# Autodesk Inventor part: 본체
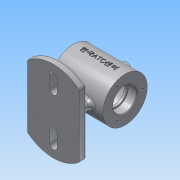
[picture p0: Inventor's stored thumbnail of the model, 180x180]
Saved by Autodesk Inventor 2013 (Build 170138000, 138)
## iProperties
Created: 2017-12
Part Number: 본체
Material: 알루미늄 6061
Document SubType Name: Modeling
Designer: Administrator
Density: 2.71 g/cm^3
Mass: 467.691 g
Surface Area: 486.474 cm^2
Volume: 172.58 cm^3
Author: Administrator
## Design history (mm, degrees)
sketch "스케치1"
  geometry: L1 (0, 30)-(0, 25); L2 (0, 25)-(-17, 25); L3 (-20, 22)-(-20, 14); L4 (-20, 14)-(-23, 14); L5 (-23, 14)-(-23, 15.7); L6 (-23.3, 16)-(-34, 16); L7 (-35, 17)-(-35, 30); L8 (-35, 30)-(0, 30); L9 (-35, 0)-(0, 0); L10 (-34, 16)-(-35, 17); A1 r 3 centre (-17, 22) between (-17, 25) and (-20, 22); A2 r 0.3 centre (-23.3, 15.7) between (-23, 15.7) and (-23.3, 16); 4 further points
  constraints: 20 end point, 6 parallel, 4 point on circle, 4 point on line, 4 tangent, 2 centre point, 2 midpoint, 2 perpendicular, 2 vertical alignment, 1 vertical
  dimensions: "d0" = 35 distance of L9.start L9.end; "d1" = 60 diameter of L8 L9; "d2" = 50 diameter of L2 L9; "d3" = 32 diameter of L6 L9; "d4" = 12 distance of point (-23, 16) point (-35, 16); "d5" = 28 diameter of L4 L9; "d6" = 3 distance of L3.end L4.end; "d7" = 3 radius of A1; "d8" = 0.3 radius of A2; "d9" = 1 distance of L6.end point (-35, 16); "d10" = 1 distance of L7.start point (-35, 16) (= d9)
revolve "회전1" sketch "스케치1" stored, may be unused: angle "d11" = 90 deg
node "작업 평면1"
sketch "스케치2"
  geometry: L1 (35, -42.426)-(35, 42.426); L2 (-35, -42.426)-(-35, 42.426); L3 (0, -55)-(0, 55); L4 (35, 0)-(-35, 0); A1 r 55 centre (0, 0) between (35, 42.426) and (-35, 42.426); A2 r 55 centre (0, 0) between (-35, -42.426) and (35, -42.426); 2 further points
  constraints: 8 end point, 6 point on circle, 3 midpoint, 2 centre point, 2 coincident, 2 parallel, 1 vertical, 1 vertical alignment, 1 other
  dimensions: "d14" = 70 distance between parallel lines of L2 L1; "d15" = 55 radius of A2
extrude "돌출1" join sketch "스케치2" distance "d16" = 10; taper "d17" = 0 deg
sketch "스케치3"
  geometry: L1 (35, -42.426)-(35, 42.426) reference; L2 (-5, 40)-(-5, 24); L3 (5, 24)-(5, 40); L4 (-5, -24)-(-5, -40); L5 (5, -40)-(5, -24); L6 (-15, 5)-(15, 5); L7 (15, -5)-(-15, -5); L8 (0, 55)-(0, -55); A1 r 55 centre (0, 0) between (-35, -42.426) and (35, -42.426) reference; A2 r 55 centre (0, 0) between (35, 42.426) and (-35, 42.426) reference; A3 r 5 centre (0, 24) between (-5, 24) and (5, 24); A4 r 5 centre (0, 40) between (5, 40) and (-5, 40); A5 r 5 centre (0, -40) between (-5, -40) and (5, -40); A6 r 5 centre (0, -24) between (5, -24) and (-5, -24); A7 r 5 centre (15, 0) between (15, -5) and (15, 5); A8 r 5 centre (-15, 0) between (-15, 5) and (-15, -5)
  constraints: 14 end point, 14 point on circle, 12 tangent, 6 centre point, 5 parallel, 2 perpendicular, 2 vertical alignment, 1 equal radius, 1 horizontal alignment, 1 other
  dimensions: "d18" = 5 radius of A4; "d20" = 16 distance of A4.centre A3.centre; "d21" = 16 distance of A5.centre A6.centre; "d22" = 24 distance of A3.centre A1.centre; "d23" = 24 distance of A6.centre A1.centre; "d24" = 5 radius of A8; "d25" = 30 distance of A7.centre A8.centre
extrude "돌출2" cut sketch "스케치3" stored distance "d26" = 10; taper "d27" = 0 deg
extrude "돌출3" join sketch "스케치3" stored distance "d28" = 10; taper "d29" = 0 deg
fillet "모깎기1" dims "d30" = 5
node "작업 평면2"
sketch "스케치4"
  geometry: C1 r 8 at (0, 0); 1 further point
  constraints: 1 centre point, 1 coincident
  dimensions: "d32" = 16 diameter of C1
extrude "돌출4" join sketch "스케치4" stored distance "d34" = 10; taper "d35" = 0 deg
hole "구멍1" diameter "d38" = 8; stored, may be unused: countersink angle "d42" = 90 deg, drill point angle "d44" = 0 deg; dims "d36" = 10, "d37" = 10, "d39" = 6, "d40" = 4, "d41" = 2, "d43" = 8
chamfer "모따기1" distance "d45" = 1; stored, may be unused: second distance "d46" = 2, angle "d47" = 45 deg
sketch "스케치5" dims "d48" = 46
  geometry: C1 r 30 at (0, 0) reference; C2 r 17 at (0, 0) reference; 2 further points
  constraints: 2 vertical alignment, 1 coincident, 2 other
hole "구멍2" sketch "스케치5" at (0, 23) diameter "d49" = 3.242; stored, may be unused: countersink angle "d53" = 90 deg, drill point angle "d55" = 118 deg; dims "d50" = 8, "d51" = 4, "d52" = 2, "d54" = 10
node "작업 평면3"
sketch "스케치6"
  geometry: 2 further points
  constraints: 1 other
feature "엠보싱1" sketch "스케치6" dims "d12" = -62, "d60" = 0.5, "d61" = 0
fillet "모깎기2" dims "d62" = 3
node "솔리드1"
mirror "대칭1"
pattern_circular "원형 패턴1" dims angle "d57" = 360 deg
mirror "대칭2"
other parameters: "d31" = 37
